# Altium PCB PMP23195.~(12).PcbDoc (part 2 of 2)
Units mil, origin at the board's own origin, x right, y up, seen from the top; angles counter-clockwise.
Board outline 3600 x 3375 mil, 4 copper layers (Top Layer, Signal Layer 1, Signal Layer 2, Bottom Layer), stack 39.6 mil thick; 101 components, 57 nets, 256 pads, 67 vias.
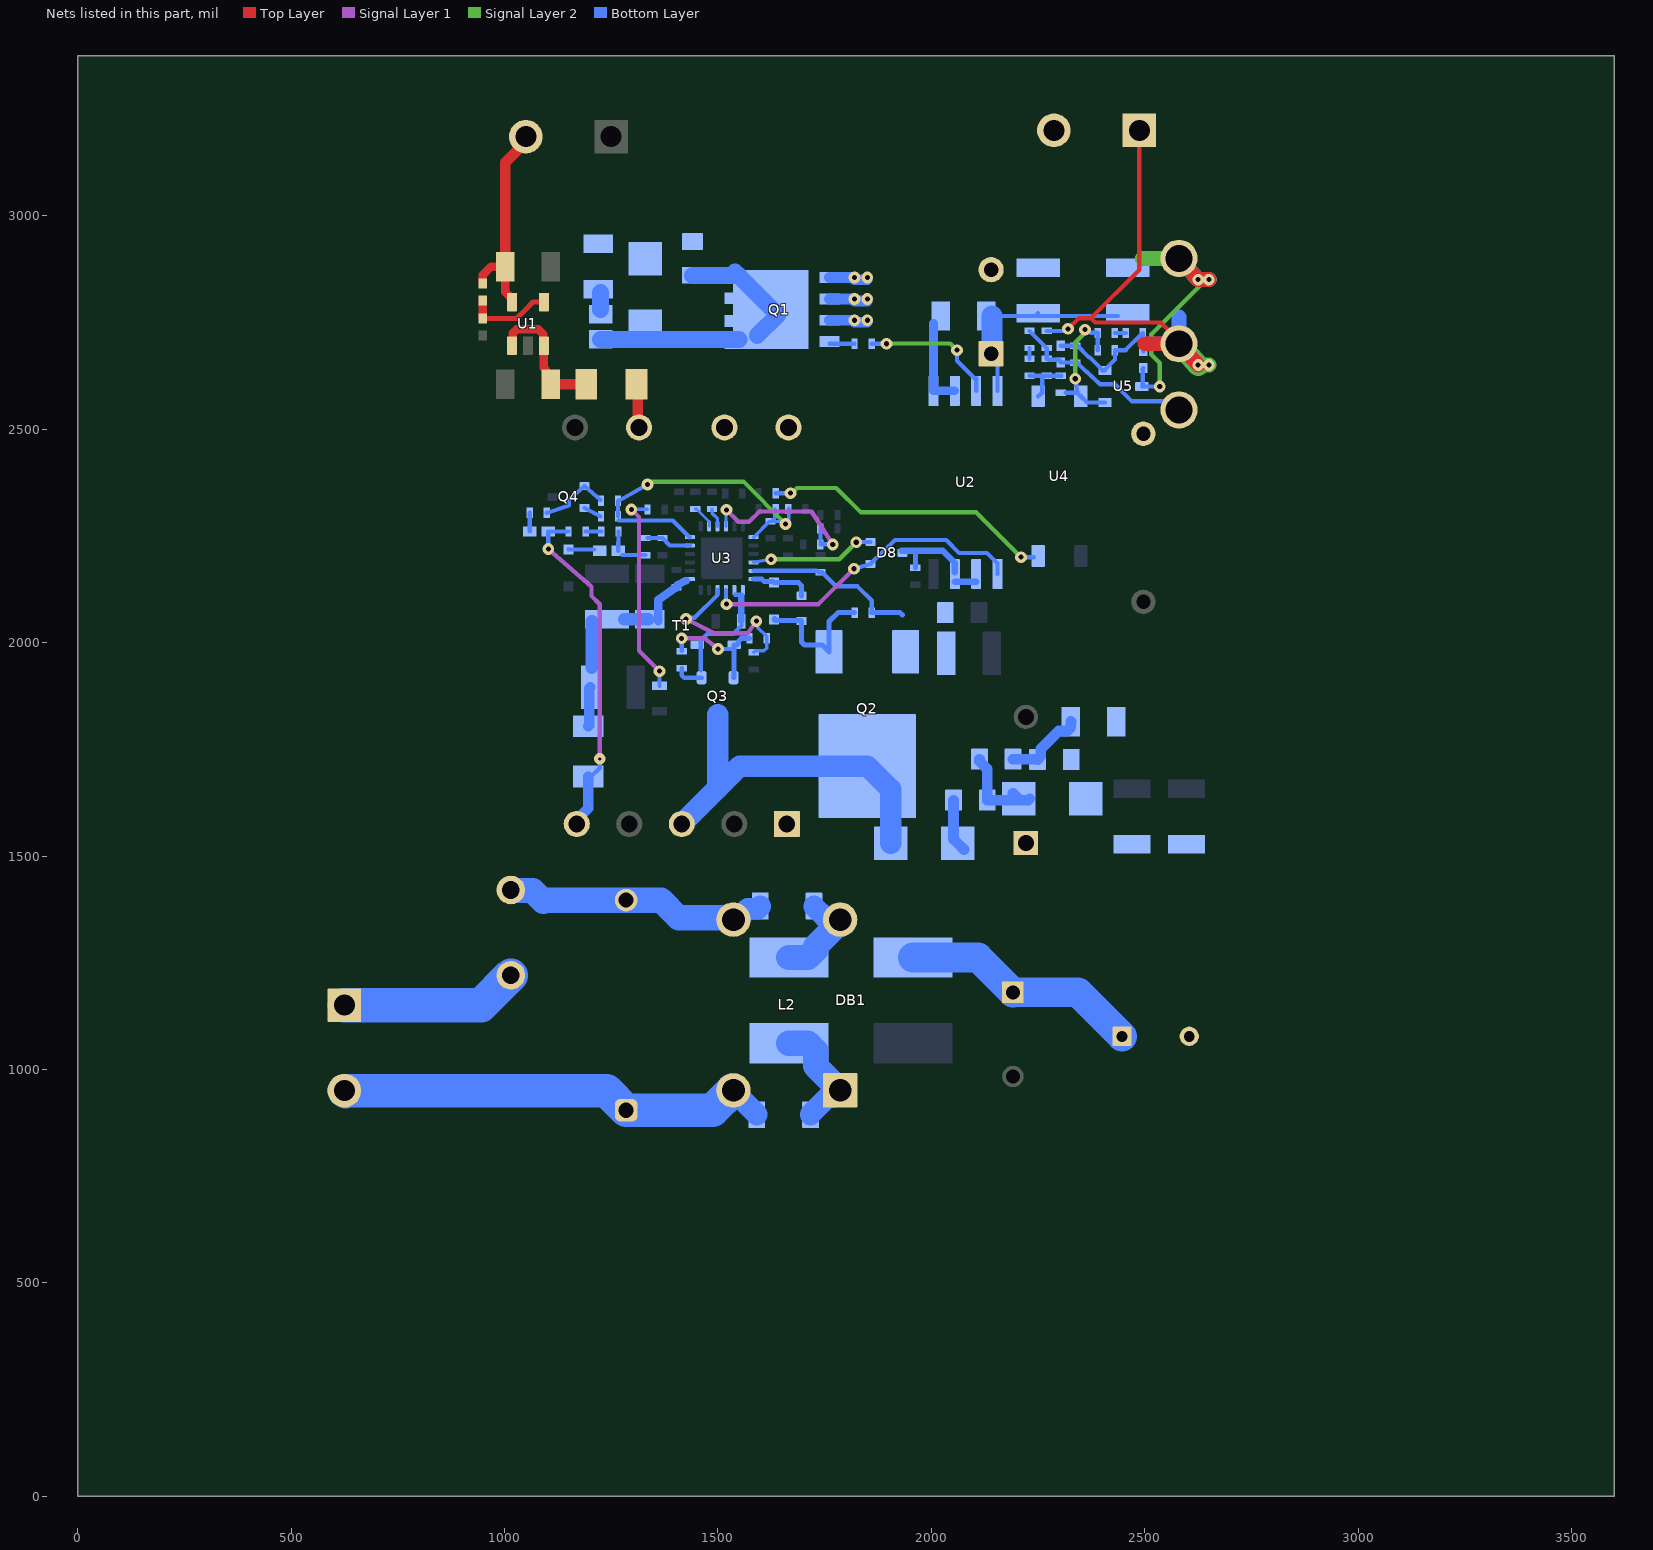
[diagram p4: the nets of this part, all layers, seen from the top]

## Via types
v1: diameter 27.56, hole 11.81, Top Layer to Bottom Layer, tented both sides, 30 vias
v2: diameter 27.56, hole 11.81, Top Layer to Bottom Layer, tented top, 20 vias
v3: diameter 19.68, hole 7.87, Top Layer to Bottom Layer, 5 vias
v4: diameter 24, hole 8, Top Layer to Bottom Layer, tented both sides, 4 vias
v5: diameter 27, hole 8, Top Layer to Bottom Layer, tented both sides, 4 vias
v6: diameter 27.56, hole 11.81, Top Layer to Bottom Layer, 4 vias

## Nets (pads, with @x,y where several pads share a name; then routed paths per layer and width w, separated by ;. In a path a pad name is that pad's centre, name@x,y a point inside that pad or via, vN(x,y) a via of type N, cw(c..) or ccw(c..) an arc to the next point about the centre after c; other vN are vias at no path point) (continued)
GND_S: C1.1 C8.2 C9.2 C10.2 C11.2 C20.2 D4.2 J2.2 Q1.1 Q1.2 Q1.3 R4.1 R36.1 TP2.1 U2.5 U2.6 U5.3 | length 1409.8
  Top Layer w35: TP2.1@2580,2900 v6(2625,2850) v6(2650,2850)
  Signal Layer 1 w35: TP2.1@2580,2900 v6(2625,2850) v6(2650,2850)
  Signal Layer 2 w10: v1(2535,2600) 2535,2655 2515,2675 2515,2722 v6@2641.5,2848.5
  Signal Layer 2 w35: 2495,2900 TP2.1@2580,2900 v6(2625,2850) v6(2650,2850)
  Bottom Layer w10: R36.1@2496.65,2643.31 2494.98,2641.63 2494.98,2601.67 U5.3@2493.31,2600 v1(2535,2600)
  Bottom Layer w20: C20.2@2005,2748.43 U2.5@2005,2589.57 U2.6@2055,2589.57
  Bottom Layer w25: Q1.3@1761.22,2755 v2(1820,2755) ; Q1.2@1761.22,2805 v2(1820,2805) ; Q1.1@1761.22,2855 v2(1820,2855) ; v2@1820,2750 v2@1850,2750 ; v2@1820,2800 v2@1850,2800 ; v2@1820,2850 v2@1850,2850 ; v6(2625,2850) v6(2650,2850)
  Bottom Layer w35: 2495,2900 TP2.1@2580,2900 v6(2625,2850)
  other v2: 1850,2755 1850,2805 1850,2855
IPC: R32.1 R34.2 U3.4 | length 418
  Signal Layer 1 w10: v1(1519.8,2310.91) 1548,2283 1572.52,2283 1597.27,2307 1719,2307 v1(1769,2230)
  Bottom Layer w7.87: U3.4@1518.81,2272.53 1518.81,2309.92 v1(1519.8,2310.91)
  Bottom Layer w10: R32.1@1740,2230 v1@1775,2230 ; R32.1@1740,2235 R34.2@1740,2267
NetC2_2: C2.2 R1.1 R2.2 | length 190.4
  Bottom Layer w25: R2.2@2191.37,1726.98 2191.73,1726.62 2248.45,1726.62 R1.1@2248.81,1726.26 2256,1733.44 2256,1750.87 2298.17,1793.05 2317.7,1793.05 2326.85,1802.2 C2.2@2326.85,1815 C2.2@2326.99,1814.86
NetC6_1: C6.1 J1.2 L2.2 R38.1 | length 1033.3
  Bottom Layer w50: L2.2@1536.31,951.02 1536.31,949.88 1591.01,895.18 R38.1@1591.01,894
  Bottom Layer w78.74: J1.2@627.75,947.72 J1.2@625,950.47 1238.94,950.47 C6.1@1285,904.41 1487.41,904.41 1533.65,950.65 1535.93,950.65 L2.2@1536.31,951.02
NetC6_2: C6.2 F1.1 L2.3 R37.1 | length 629
  Bottom Layer w50: L2.3@1536.31,1351.02 1544.62,1351.02 1570.1,1376.5 1593.9,1376.5 1599.21,1381.82 R37.1@1599.21,1383
  Bottom Layer w59.06: F1.1@1015,1420.47 1016.51,1418.97 1066.03,1418.97 1091,1394 1093.54,1396.54 C6.2@1285,1396.54 1366.83,1396.54 1408.19,1355.17 1532.16,1355.17 L2.3@1536.31,1351.02
NetC7_1: C7.1 DB1.1 L1.1 | length 566.3
  Bottom Layer w70: DB1.1@1957.34,1262.25 2109.18,1262.25 C7.1@2191,1180.43 ; C7.1@2190.68,1180.99 2343.24,1180.99 L1.1@2446.59,1077.65
NetC11_1: C11.1 C12.2 D4.1 Q1.5 Q1.6 Q1.7 Q1.8 Q1.9 T1.8 | length 645.8
  Bottom Layer w39.37: C12.2@1225,2710 1500,2710 1525,2710 Q1.9@1550,2710 ; C11.1@1440,2860 1525,2860 Q1.9@1550,2860 ; Q1.9@1539.77,2868.47 1640.44,2767.8 Q1.9@1592.02,2719.38
NetC12_1: C12.1 R4.2 | length 40
  Bottom Layer w39.37: C12.1@1225,2780 R4.2@1225,2820
NetC15_1: C15.1 D6.1 U1.1 U1.3 | length 318.5
  Top Layer w20: U1.1@1017.6,2695.32 1019.41,2697.13 1019.41,2724.58 1029.31,2734.48 1078.87,2734.48 1090.59,2722.77 1090.59,2697.13 U1.3@1092.4,2695.32 1092.4,2643.67 1096.5,2639.57 1096.5,2616.65 C15.1@1108.15,2605
  Top Layer w25: C15.1@1108.15,2605 D6.1@1191.5,2605
NetC21_1: C21.1 D8.3 U2.2 U2.3 | length 249.6
  Bottom Layer w12: 1960,2215 1962.37,2212.63 C21.1@1962.37,2175
  Bottom Layer w15: D8.3@1930,2215 1960,2215 2027,2215 2055,2186.94 U2.3@2055,2165 ; U2.3@2055,2142 U2.2@2105,2142
NetC24_1: C24.1 R28.2 | length 25
  Bottom Layer w10: R28.2@2230,2665 C24.1@2230,2690
NetC28_1: C28.1 C29.2 R30.1 R35.2 R36.2 U5.2 | length 314.7
  Bottom Layer w10: R30.1@2303.15,2695.35 2303.31,2695.51 C28.1@2333.09,2695.51 ; C28.1@2337.06,2695.67 2333.25,2695.67 C28.1@2333.09,2695.51 ; R36.2@2496.65,2682.68 2496.65,2684.65 2495.83,2685.47 2495.83,2724.17 R35.2@2495,2725 2455,2685 C29.2@2430,2685 2430,2663.13 2406.69,2639.82 U5.2@2406.69,2637.4 2399.71,2637.4 2399.71,2639.46 2371.5,2667.67 2369.55,2667.67 2341.72,2695.51 C28.1@2333.09,2695.51
NetC29_1: C29.1 C30.2 R33.1 U4.3 U5.1 | length 331
  Signal Layer 2 w10: v1(2337,2618) 2337.09,2703 2360,2725.91 v1(2360,2733)
  Bottom Layer w10: R33.1@2315,2585 U4.3@2342.01,2585 ; v1(2337,2618) U4.3@2342.01,2585 ; v1(2360,2733) 2373.02,2725.91 2389.09,2725.91 C30.2@2390,2725 C29.1@2390,2685 ; U5.1@2406.69,2562.6 2364.41,2562.6 U4.3@2350,2577.01 U4.3@2342.01,2585
NetC30_1: C30.1 R35.1 | length 25
  Bottom Layer w10: C30.1@2430,2725 R35.1@2455,2725
NetD1_1: D1.1 R2.1 R3.2 | length 223.6
  Bottom Layer w25: R2.1@2112.63,1726.98 2112.63,1722.05 2130.66,1704.02 R3.2@2130.66,1630.74 2227,1630.74 D1.1@2230.63,1634.37 ; D1.1@2191.26,1647.37 D1.1@2204.26,1634.37
NetD2_1: D2.1 R3.1 | length 125.8
  Bottom Layer w25: R3.1@2051.92,1630.74 2051.92,1539.83 D2.1@2061.92,1529.83 D2.1@2076.57,1515.19
NetD5_2: D5.2 Q2.1 R6.2 R7.2 | length 331.4
  Bottom Layer w12: D5.2@1632.97,2055.66 D5.2@1631,2053.69 1632.61,2052.08 1694.39,2052.08 R6.2@1696,2050.47 1696,2001.51 1703.03,1994.48 1744.12,1994.48 Q2.1@1760.24,1978.37 1760.24,2049.24 1781,2070 R7.2@1820.31,2070
NetD6_2: D6.2 T1.7 | length 103.4
  Top Layer w25: D6.2@1309.61,2605 1312.46,2602.15 1312.46,2506.85 T1.7@1315.31,2504
NetD7_1: D7.1 Q3.2 R8.1 R12.2 | length 280.8
  Signal Layer 1 w10: v1(1415,2010) 1468.25,2010 v1(1500,1985)
  Bottom Layer w10: R8.1@1415,1980 v1(1415,2010) ; v1(1500,1985) 1535,1985
  Bottom Layer w12: Q3.2@1536.6,1917.76 1537.45,1918.61 1537.45,1994.15 1543.36,1994.15 1548.06,1998.84 1548.06,2002.97 1555.08,2010 R12.2@1573.9,2010
NetD9_1: D9.1 R17.2 R19.1 | length 99
  Bottom Layer w10: D9.1@1266.65,2215 R17.2@1267,2260 ; D9.1@1276,2205 R19.1@1330,2205
NetD9_2: D9.2 D11.2 | length 60
  Bottom Layer w10: D11.2@1150,2218.31 D9.2@1210,2218
NetD10_1: D10.1 R20.2 | length 44
  Bottom Layer w10: R20.2@1059,2304 D10.1@1059.35,2260
NetDB1_2: DB1.2 L2.4 R37.2 | length 240.2
  Bottom Layer w50: R37.2@1725.2,1383 1725.2,1381.82 1750.12,1356.9 1780.43,1356.9 L2.4@1786.31,1351.02
  Bottom Layer w59.06: DB1.2@1666,1262.25 1711.28,1262.25 1728.99,1279.96 1728.99,1287.85 1786.31,1345.16 L2.4@1786.31,1351.02
NetDB1_3: DB1.3 L2.1 R38.2 | length 280.4
  Bottom Layer w50: R38.2@1716.99,894 1716.99,895.18 1757.48,935.67 1770.95,935.67 L2.1@1786.31,951.02
  Bottom Layer w59.06: DB1.3@1666,1061.46 1711.28,1061.46 1728.99,1043.74 1728.99,1008.34 L2.1@1786.31,951.02
NetF1_2: F1.2 J1.1 | length 419
  Bottom Layer w80: J1.1@625,1150.47 945,1150.47 F1.2@1015,1220.47
NetQ1_4: Q1.4 R5.2 | length 58.8
  Bottom Layer w10: Q1.4@1761.22,2700 R5.2@1820,2700
NetQ4_1: Q4.1 R16.2 R20.1 | length 166.2
  Bottom Layer w10: R20.1@1099,2304 1150.94,2321 1150.94,2335 Q4.1@1187.42,2366.59 R16.2@1224.37,2334
NetQ4_2: Q4.2 R15.2 | length 41.7
  Bottom Layer w10: Q4.2@1187.42,2315.41 R15.2@1224.37,2296
NetR9_1: R9.1 R13.2 U1.4 | length 201.9
  Top Layer w12: R13.2@949,2758.98 1028.16,2758.98 1047.9,2778.72 1066.86,2797.68 U1.4@1092.4,2797.68
  Top Layer w20: R13.2@949,2758.98 R9.1@949,2801.49
NetR14_2: R14.2 R17.1 | length 37
  Bottom Layer w10: R14.2@1190,2260 R17.1@1227,2260
NetR26_1: R26.1 R28.1 R33.2 U4.1 | length 127.8
  Bottom Layer w10: R28.1@2230,2625 R26.1@2270,2625 R33.2@2305,2625 ; U4.1@2250,2577.01 2260,2585 R26.1@2260,2625
OPTO_C: R21.2 U4.6 | length 676
  Signal Layer 2 w10: v1(1670,2350) 1685,2362 1777,2362 1835,2305 2105,2305 v2(2210,2200)
  Bottom Layer w10: R21.2@1635,2350 v1(1670,2350) ; v2(2210,2200) U4.6@2240,2200
P13: C23.1 D7.2 Q3.1 R8.2 U3.13 U3.14 | length 320.3
  Bottom Layer w10: R8.2@1415,1940 1415,1923.61 1420.86,1917.76 Q3.1@1461.79,1917.76 ; 1460,1935 1460,2005 1475,2020 1535,2020 C23.1@1555,2040 ; U3.14@1540,2112 U3.13@1556.22,2111.97
  Bottom Layer w15: C23.1@1555,2050 1555,2109
PWML: D5.1 R6.1 U3.12 | length 142.3
  Bottom Layer w12: U3.12@1583.77,2148.51 1602.65,2148.51 1608.39,2142.77 1628.53,2142.77 D5.1@1631,2140.31 1688.97,2140.31 1696,2133.28 R6.1@1696,2109.53
QLSRC: Q2.3 R7.1 R10.1 R11.2 R23.2 U3.11 | length 408.3
  Bottom Layer w10: U3.11@1583.77,2168.2 1731.71,2168.2 1735.5,2164.41 R23.2@1740,2164.41 1744.5,2164.41 1777.22,2131.69 1827.2,2131.69 1860.31,2098.59 R7.1@1860.31,2070
  Bottom Layer w12: R7.1@1860.31,2070 1926.91,2070 1932.4,2064.5
RDM: R31.2 U3.3 | length 45.8
  Bottom Layer w7.87: R31.2@1485.96,2312.88 1485.96,2303.52 1499.12,2290.36 U3.3@1499.12,2272.53
REF: C22.1 C31.1 R15.1 R16.1 R24.1 U3.7 U3.24 | length 839.7
  Signal Layer 2 w9.84: 1560,2377 v1(1658,2278) ; v1@1659.44,2269.49 v1@1664.53,2274.58
  Signal Layer 2 w10: v1@1340,2377 1560,2377
  Bottom Layer w8: U3.7@1583.77,2246.94 1620.5,2283.67 C31.1@1624.99,2283.67 ; C22.1@1634.9,2312.88 1632.61,2312.88 1632.61,2291.29 C31.1@1624.99,2283.67 ; R24.1@1665.76,2314.85 1665.76,2275.81 1664.53,2274.58 1655.44,2283.67 C31.1@1624.99,2283.67
  Bottom Layer w9.84: U3.24@1432.72,2246.94 U3.24@1434.16,2246.94
  Bottom Layer w10: R15.1@1266,2296 R16.1@1266,2332 ; R16.1@1266,2331 v1(1335,2370) ; R15.1@1267.65,2286 1394,2286 U3.24@1432.72,2246.94
RT1_1: R27.1 RT1.1 | length 487.6
  Signal Layer 1 w9.84: v1(1297,2312) 1315,2294 ; v1@1297.34,2310.91 v1@1306.49,2310.91
  Signal Layer 1 w10: 1315,2294 1315,1981 v1(1363,1933)
  Bottom Layer w8: v1(1297,2312) R27.1@1335,2312
  Bottom Layer w10: RT1.1@1362.93,1898.9 v1(1363,1933)
RTZ: R29.2 U3.2 | length 56
  Bottom Layer w6: R29.2@1446.59,2312.88 1450.15,2312.88 1479.44,2283.59 U3.2@1479.44,2272.53
RUN: D8.2 U3.10 | length 301.1
  Signal Layer 2 w9.84: v1(1624.74,2195.03) 1784,2195
  Signal Layer 2 w10: 1784,2195.03 v1(1824,2235)
  Bottom Layer w7.87: U3.10@1583.77,2187.88 v1(1624.74,2195.03) v1@1617.59,2187.88
  Bottom Layer w10: v1(1824,2235) D8.2@1857.6,2235.59
SR_DRV: R5.1 U2.7 | length 325.9
  Signal Layer 2 w10: v1(1895,2700) 1895.7,2700.7 2044.3,2700.7 v1(2060,2685)
  Bottom Layer w10: R5.1@1860,2700 v1(1895,2700) ; v1(2060,2685) 2060,2660 U2.7@2105,2615 ; U2.7@2105,2589.57 U2.7@2105,2620
SRDRV: D8.1 U2.1 U3.15 | length 773.7
  Signal Layer 1 w10: v1(1520,2090) 1735.67,2090 v1(1818.64,2172.96)
  Bottom Layer w10: v1@1519,2090 U3.15@1519,2123 ; v1(1818.64,2172.96) D8.1@1857.6,2184.41 1915,2240 2035,2240 2065,2210 2130,2210 U2.1@2155,2185 ; U2.1@2155,2160.43 U2.1@2155,2184.84
SWS: C16.2 R12.1 U3.16 | length 403.4
  Signal Layer 1 w10: v1(1425,2055) 1490,2022 1570,2022 v1(1590,2050)
  Bottom Layer w8: C16.2@1583.77,1977 1587.27,1980.5 1607.58,1980.5 1613.9,1986.82 R12.1@1613.9,2010 1613.9,2014.5 1593.74,2034.66 1593.74,2046.26 v1(1590,2050)
  Bottom Layer w10: v1(1425,2055) 1428.36,2058.36 1445.8,2058.36 1499.12,2111.68 U3.16@1499.12,2122.92
Vaux: D3.2 D10.2 R14.1 T1.5 | length 812.7
  Signal Layer 1 w10: v1(1102.65,2219) 1204,2130.77 1204,2109.23 1223.35,2089.88 v5(1223.35,1727.31)
  Bottom Layer w10: v1(1102.65,2219) D10.2@1102.65,2260 R14.1@1150,2260 ; D3.2@1196.18,1685.94 1202.76,1685.94 1223.35,1706.54 v5(1223.35,1727.31)
  Bottom Layer w25: T1.5@1169.31,1575 1169.31,1584.75 1196.18,1611.62 D3.2@1196.18,1685.94
Vbulk: C2.1 C3.2 C4.2 C5.2 D1.2 L1.2 R1.2 T1.1
VDD: C13.2 C17.1 C18.1 C19.2 D3.1 U3.19 | length 380.9
  Bottom Layer w18: C17.1@1405,2135 U3.19@1425,2145
  Bottom Layer w20: C18.1@1360,2050 1360,2100 C17.1@1403,2130
  Bottom Layer w25: D3.1@1196.18,1804.06 1198.59,1806.46 1198.59,1892.59 C13.2@1201,1895
  Bottom Layer w30: C13.2@1204.46,1941.82 C19.2@1205,2050 ; C19.2@1281.04,2054.85 C18.1@1336.04,2054.85
VOUT: C8.1 C9.1 C10.1 C20.1 J2.1 R18.1 T1.9 TP1.1 U2.8 | length 1910.8
  Top Layer w10: v1(2320,2735) 2346,2760 2374,2760 ; J2.1@2487,3200 2487,2873 2374,2760 ; TP1.1@2580,2700 2580,2706.97 2537.36,2750 2384,2750.05 2374,2760
  Top Layer w20: v6(2625,2650) v6(2650,2650)
  Top Layer w35: 2500,2700 TP1.1@2580,2700 v6(2625,2650)
  Signal Layer 1 w20: v6(2625,2650) v6(2650,2650)
  Signal Layer 1 w35: 2505,2700 TP1.1@2580,2700 v6(2625,2650)
  Signal Layer 2 w35: v6(2625,2650) v6(2650,2650)
  Signal Layer 2 w50: TP1.1@2580,2700 v6(2625,2650)
  Bottom Layer w10: C10.1@2141.93,2678.5 C10.1@2140,2676.57 2155,2661.57 U2.8@2155,2589.57 ; C20.1@2141.93,2765 C8.1@2243.15,2765 ; C8.1@2250,2771.85 C8.1@2243.15,2765 ; R18.1@2270,2730 2310,2730 v1(2320,2735) ; C9.1@2436.8,2765 C8.1@2243.15,2765
  Bottom Layer w25: v6@2625.32,2650 v6(2650,2650)
  Bottom Layer w35: 2580,2762.93 TP1.1@2580,2700 v6(2625,2650)
  Bottom Layer w50: C10.1@2141.93,2678.5 C20.1@2141.93,2765
VOUT2: C14.1 J3.2 R9.2 U1.5 | length 496.5
  Top Layer w20: R9.2@949,2840.86 949,2861.29 968.54,2880.83 C14.1@1001.85,2880.83 1001.85,2821.05 1013.57,2809.34 1015.79,2809.34 1017.6,2807.53 U1.5@1017.6,2797.68
  Top Layer w25: C14.1@1001.85,2880.83 1001.85,3124.44 1050,3172.59 J3.2@1050,3185
VOUT_A: C24.2 C28.2 R18.2 R26.2 R30.2 TP3.1 | length 443.3
  Bottom Layer w10: C24.2@2230,2730 R18.2@2270,2690 R26.2@2270,2666.65 ; R26.2@2270,2665 R26.2@2270,2666.65 ; R30.2@2303.15,2655.98 R30.2@2303.15,2657.66 ; TP3.1@2580,2545 2560,2565 2470,2565 2430,2605 2395.28,2605 2365,2634 2363.23,2634 2341.4,2655.83 2304.98,2655.83 R30.2@2303.15,2657.66 ; R26.2@2270,2666.65 2274.15,2662.5 2298.31,2662.5 R30.2@2303.15,2657.66
VS: R19.2 R22.2 U3.23 | length 106.7
  Bottom Layer w10: R19.2@1335,2245 R22.2@1370,2245 1387,2227.25 U3.23@1434.16,2227.25
Vswn: D2.2 Q2.2 Q3.3 T1.3 | length 866.5
  Bottom Layer w50: T1.3@1415.31,1575 1499.2,1658.89 ; Q3.3@1499.2,1831.14 1499.2,1658.89 ; D2.2@1904.44,1529.83 1904.44,1656.21 Q2.2@1850,1710.65 1550.96,1710.65 1499.2,1658.89
pads on no net: T1.2

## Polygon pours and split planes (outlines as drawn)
GND_P on Bottom Layer "BOTTOM_LAYER_GND_P_P296" (solid, remove dead copper, pour order 296): 2598.51,1797 2634.79,1797 2635.32,1870 2635.32,2030 2000.93,2030 2000.93,1797
GND_S on Bottom Layer "BOTTOM_LAYER_GND_S_P335" (solid, remove dead copper, pour order 335): 2239.06,3375 2670.99,3375 2670.99,2938 2239.06,2938
NetC11_1 on Bottom Layer "BOTTOM_LAYER_NETC11_1_P334" (solid, remove dead copper, pour order 334): 1434.16,2678.5 1432.72,2677.07 1432.72,2519.75 1487.47,2465 1535,2465 1583.77,2513.77 1583.77,2675.67
Vbulk on Bottom Layer "BOTTOM_LAYER_VBULK_P330" (solid, remove dead copper, pour order 330): 2190.68,1486.26 2356.95,1320 2424.5,1320 2540,1204.5 2540,1050 2566.21,1023.79 2647.11,1023.79 2647.11,1480.01
GND_P on Bottom Layer "BOTTOM_LAYER_GND_P_P329" (solid, remove dead copper, pour order 329): 1254.15,1948.15 1246.95,1940.96 1246.95,1847.07 1260,1834.03 1260,1548.88 1269.05,1539.83 1322.66,1539.83 1339,1556.17 1339,1766.86 1394,1821.86 1394,1857.51 1381.51,1870 1360,1870 1360,1870.82 1339,1891.82 1339,1957 1261.03,1957 1254.15,1950.12
GND_P on Bottom Layer "BOTTOM_LAYER_GND_P_P328" (solid, remove dead copper, pour order 328): 2091.29,2117.58 2091.29,1970.89 2087.98,1967.58 2088.48,1967.08 2260,1967.08 2260,2002 2134.99,2127.01 2134.18,2126.2 2085.15,2126.2
GND_P on Bottom Layer "BOTTOM_LAYER_GND_P_P306" (solid, remove dead copper, pour order 306): 1950,2150 1950,2098.54 2147.09,2098.54 2147.09,2150
QLSRC on Bottom Layer "BOTTOM_LAYER_QLSRC_P327" (solid, remove dead copper, pour order 327): 2072.02,2102.03 1907.03,2102.03 1888.41,2083.41 1888.41,1922.4 1895,1915.82 2056.89,1915.82 2072.02,1930.95
GND_P on Bottom Layer "BOTTOM_LAYER_GND_P_P325" (solid, remove dead copper, pour order 325): 2401.69,1611.26 2401.69,1704.56 2429.56,1704.56 2479.8,1754.8 2479.8,2030 2482.14,2027.66 2647.11,2027.66 2647.11,1611.26
Vbulk on Bottom Layer "BOTTOM_LAYER_VBULK_P324" (solid, remove dead copper, pour order 324): 2401.69,1611.26 2650.36,1611.26 2652.27,1609.35 2650,1607.07 2650,1469.17 2207.78,1469.17 2204.26,1472.69 2342.26,1610.69 2342.84,1610.69
Vbulk on Bottom Layer "BOTTOM_LAYER_VBULK_P323" (solid, remove dead copper, pour order 323): 2380,1850.43 2380,1767.48 2367.32,1754.8 2308.08,1754.8 2282.13,1728.85 2282.13,1608 2221.3,1547.17 2203.01,1547.17 2190.68,1534.85 2190.68,1486.26 2204.26,1472.69 2282.85,1472.69 2420,1609.83 2420,1695 2470,1745 2470,1850.06
GND_P on Bottom Layer "BOTTOM_LAYER_GND_P_P319" (solid, remove dead copper, pour order 319): 1867.07,1151.02 2066.22,1151.02 2117.25,1100 2242.34,1100 2252.34,1090 2252.34,952.34 2230,930 1909.76,930 1867.07,972.69
VOUT on Bottom Layer "BOTTOM_LAYER_VOUT_P314" (solid, remove dead copper, pour order 314): 2655,2820 2655,2630 2515,2630 2515,2755 2110,2755 2110,2820
NetC11_1 on Bottom Layer "Bottom Layer-NetC33_2" (solid, pour order 303): 1395,2660 1395,2900 1720,2900 1720,2660
GND_S on Bottom Layer "Bottom Layer-SGND" (solid, remove dead copper, pour order 307): 1184.57,2980 1184.57,2915 1733.02,2915 1733.02,2726.26 2050,2726.26 2050,2830 2655,2830 2655,2960 2635,2980
GND_S on Signal Layer 2 "SIGNAL_LAYER_2_GND_S_P338" (solid, remove dead copper, pour order 338): 2260,3375 2260,2869.98 2653,2869.98 2653,3375
GND_S on Signal Layer 2 "Signal Layer 2-SGND" (solid, pour order 292): 1274.79,2823.51 1274.79,2672.12 1471.92,2475 2495,2475 2495,2725 2605,2835 2654,2835 2654,2915 2654,2965 2638.62,2980.38 1431.33,2980.05
GND_P on Signal Layer 2 "SIGNAL_LAYER_2_GND_P_P293" (solid, remove dead copper, pour order 293): 1374.42,2365 1374.42,1541.23 2650,1541.23 2650,2143.51 2428.51,2365
GND_P on Signal Layer 2 "SIGNAL_LAYER_2_GND_P_P291" (solid, remove dead copper, pour order 291): 928,2390 928,1545.17 1765.07,1545.17 1769.08,2390
GND_P on Signal Layer 2 "SIGNAL_LAYER_2_GND_P_P290" (solid, remove dead copper, pour order 290): 1900.33,1576.66 1900.33,880 2650,880 2650,1576.66
VOUT on Signal Layer 1 "SIGNAL_LAYER_1_VOUT_P337" (solid, remove dead copper, pour order 337): 2372.3,2945.9 2374,2947.6 2374,3380.9 2680.61,3380.9 2673.28,3373.57 2673.28,2646.11 2662.31,2657.08 2386.29,2657.08
GND_C on Signal Layer 1 "SIGNAL_LAYER_1_GND_C_P332" (solid, remove dead copper, pour order 332): 1354.15,3375 1357.21,3371.94 1357.21,2988.15 1158.7,2988.15 1151.5,2980.95 1151.5,2564.5 1241,2475 920.01,2475 911.21,2483.81 911.21,3375
GND_P on Signal Layer 1 "SIGNAL_LAYER_1_GND_P_P289" (solid, remove dead copper, pour order 289): 1416.08,2301.91 1416.08,1540.41 2650,1540.41 2650,2301.91
VOUT on Signal Layer 1 "Signal Layer 1-VN" (solid, pour order 288): 1363,2519.02 1407.02,2475 2510,2475 2655,2620 2655,2747 2432,2970 1363,2970
GND_P on Signal Layer 1 "SIGNAL_LAYER_1_GND_P_P287" (solid, remove dead copper, pour order 287): 928,2389 928,1545.17 1781,1545.17 1781,2389
no net on Signal Layer 1 "SIGNAL_LAYER_1_NONET_P286" (solid, remove dead copper, pour order 286): 1900.33,1494 1900.33,880 2650,880 2650,1494
VOUT on Top Layer "TOP_LAYER_VOUT_P336" (solid, remove dead copper, pour order 336): 2374,2940 2375.7,2941.7 2375.7,3375 2682.31,3375 2674.99,3367.67 2674.99,2640.21 2664.01,2651.18 2387.99,2651.18
GND_C on Top Layer "TOP_LAYER_GND_C_P331" (solid, remove dead copper, pour order 331): 1150,3375 1118.14,3343.14 1118.14,3151.17 946.9,2979.93 915.01,2948.04 915.02,2450 920.02,2445 1265,2445 1261.03,2448.97 1261.03,2619.17 1134.5,2745.7 1134.5,2988.15 1166.35,3020 1190,3020 1341.02,3020 1354.5,3033.48 1354.5,3375
Vbulk on Top Layer "TOP_LAYER_VBULK_P322" (solid, remove dead copper, pour order 322): 1598.5,1545.17 1600,1546.67 1600,1633.29 1621.71,1655 2284.35,1655 2330,1609.35 2330,1485 2283,1438 2282.13,1438.87 1902.84,1438.87 1827.2,1514.5 1624.74,1514.5
VOUT on Top Layer "Top Layer-VN" (solid, pour order 285): 1150,2975 1150,2730.42 1246.95,2660 1600,2660 1600,2465 2500,2465 2655,2620 2655,2745 2425,2975
GND_P on Top Layer "TOP_LAYER_GND_P_P283" (solid, remove dead copper, pour order 283): 1775,2226.84 1775,1755.92 2635.32,1755.78 2635.32,2075.51 2483.98,2226.84
GND_P on Top Layer "TOP_LAYER_GND_P_P284" (solid, remove dead copper, pour order 284): 940,2390 940,1887.57 1860,1887.57 1860,2390

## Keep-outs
Keep-Out Layer:
  text ".Layer_Name" at 577,-858.49 h60

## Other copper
Top Layer:
  pour cut-out: 1245,2270 1447.21,2270 1447.21,2185.87 1347.46,2185.87 1339.83,2193.5 1245,2193.5
  pour cut-out: 2374,2772.45 2468.81,2872.24 2474,2877.44 2474,3159 2496.65,3159 2496.65,2872.24 2389.97,2765.56 2389.97,2763.03
  pour cut-out: 2380.55,2772.45 2389.97,2763.03 2547.64,2763.03 2570.31,2740.59 2547,2717.28 2529,2736.67 2358.7,2736.67 2336.23,2714.2 2295.79,2714.2 2295.79,2747.13 2318.85,2772.45
  pour cut-out: 1431.86,2328 1509,2328 1509,2259 1470,2259 1470,2284.16 1453.16,2301 1431.86,2301
  pour cut-out: 1285,2145 1205,2145 1205,2095 1235,2095 1285,2095
  pour cut-out: 1235,1930 1285,1930 1285,1845 1235,1845
  text ".Layer_Name" at 577,-858.49 h60
Signal Layer 1:
  pour cut-out: 1245,2270 1447.21,2270 1447.21,2185.87 1347.46,2185.87 1339.83,2193.5 1245,2193.5
  pour cut-out: 1245,2270 1447.21,2270 1447.21,2185.87 1347.46,2185.87 1339.83,2193.5 1245,2193.5
  pour cut-out: 2296.39,2714.17 2345,2714.17 2345,2758.48 2296.39,2758.51
  pour cut-out: 1432,2328.11 1509,2328.11 1509,2259 1470,2259 1470,2284.16 1453.16,2301 1432,2301
  pour cut-out: 1285,2145 1205,2145 1205,2095 1235,2095 1235,1845 1285,1845
Signal Layer 2:
  pour cut-out: 1245,2270 1447.21,2270 1447.21,2185.87 1347.46,2185.87 1339.83,2193.5 1245,2193.5
  pour cut-out: 1245,2270 1447.21,2270 1447.21,2185.87 1347.46,2185.87 1339.83,2193.5 1245,2193.5
  pour cut-out: 1245,2270 1447.21,2270 1447.21,2185.87 1347.46,2185.87 1339.83,2193.5 1245,2193.5
  pour cut-out: 1432,2328 1509,2328 1509,2259 1470,2259 1470,2283 1452,2301 1432,2301
  pour cut-out: 1235,1930 1285,1930 1285,1845 1235,1845
  pour cut-out: 1285,2145 1205,2145 1205,2095 1235,2095 1285,2095
Bottom Layer:
  text ".Layer_Name" at 577,-858.49 h60

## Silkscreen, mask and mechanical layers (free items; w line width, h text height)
Top Overlay:
  lines w6: 1107.26,897.53 1441.9,897.53 1441.9,1488.08 1107.26,1488.08 1107.25,897.53
  lines w7: 950,1650 950,1710
  lines w7.87: 1148.49,2393.06 1148.49,2459.5
  lines w10: 40,910 60,850 ; 40,2935 60,2995 ; 50,850 70,850 ; 50,2995 70,2995 ; 60,1647.58 60,850 ; 60,2197.42 60,2995 ; 80,910 60,850 ; 80,2935 60,2995 ; 867,3176 917,3176 ; 892,3151 892,3201 ; 915,740 915,760 ; 975,730 915,750 ; 975,770 915,750 ; 1376.6,3180.05 1426.6,3180.05 ; 1520.08,750 915,750 ; 2069.92,750 2675,750 ; 2121.07,3190 2171.07,3190 ; 2605.5,3190 2655.5,3190 ; 2615,730 2675,750 ; 2615,770 2675,750 ; 2630.5,3165 2630.5,3215 ; 2675,740 2675,760
  lines w30: 2055.47,2956.27 cw(c2140,2775) 2224.52,2956.27 ; 2107.25,902.57 ccw(c2191.77,1083.83) 2276.3,902.57
  text "DC Output" at 1471,3272 h90
  text "DC Output" at 2734,3264 h90
  text "5V,0.2A" at 1493,3168 h90
  text "12V,1.5A" at 2756,3160 h90
  text "GND_S" at 2310,2915 h40
  text "B" at 1487,2660 h40
  text "A" at 1717,2660 h40
  text "VOUT" at 2350,2645 h40
  text "2145 (mil)" at 94.99,1657.58 h60 r90
  text "+" at 2340,1270 h60
  text "LINE" at 307.73,1180 h40
  text "NEUT" at 307.73,980 h40
  text "J1: AC Input" at 250,820 h90
  text "1760 (mil)" at 1530.08,715.01 h60
  text "DANGER HIGH VOLTAGE" at 1371,577 h100
  text ".Layer_Name" at 577,-858.49 h60
Bottom Overlay:
  lines w5: 1316,2389 1315.5,2292 1325,2262 ; 1402,1993 1432,1993 ; 1412.17,2075 1441.83,2075 ; 1588.78,2399 1597,2372 ; 1638.09,2287.18 1650,2295 1650,2360 1639.83,2376 ; 1667,2034 1677,1986 ; 1719,2249 1719,2351 ; 1775.98,2318.91 1803,2340 ; 1790,2281 1814,2304 ; 2287,2678 2298.88,2739 ; 2289,2729 2316.67,2757 ; 2300.5,2569 2316.78,2548 2383,2548 2399.37,2529 ; 2329,2706.59 2351.39,2759 ; 2370,2713 2383,2750.05 2383,2836 ; 2395,2745 2395,2910 ; 2510,2725 2535,2745 ; 2511,2679 2530,2661
  lines w7: 1422,2265 1422,2284 ; 1422,2285 1442,2285
  lines w7.87: 1613.91,1351.81 1750,1352
  lines w8: 2355,1320 2385,1320 ; 2370,1305 2370,1335
  text "B" at 1387,2560 h40
  text "A" at 1870,2560 h40
  text "CAUTION" at 3400,2100 h100
  text "HOT SURFACE" at 3405,2010 h100
  text "DANGER" at 774,1372 h100
  text "HIGH VOLTAGE" at 773,1286 h100
  text "L" at 1111,1169 h100
  text "TP1" at 1110,1110 h72.83
  text "TP2" at 1110,1000 h72.83
  text "N" at 1120,916 h100
  text "DANGER" at 3500,850 h100
  text "HIGH VOLTAGE" at 3500,750 h100
  text ".Layer_Name" at 577,-858.49 h60
Top Paste:
  text ".Layer_Name" at 577,-858.49 h60
Bottom Paste:
  text ".Layer_Name" at 577,-858.49 h60
Top Solder:
  text ".Layer_Name" at 577,-858.49 h60
  text ".Layer_Name" at 577,-858.49 h60
Bottom Solder:
  text ".Layer_Name" at 577,-858.49 h60
Drill Guide:
  text ".Layer_Name" at 577,-858.49 h60
M1 Board Outline:
  drawing of 275 lines, arcs and shapes, not listed
  text ".Layer_Name" at 577,-858.49 h60
M2 Board Dimensions:
  rectangle: 125,-400 500,-275
  rectangle: 0,-275 125,-150
  lines w7: 0,-275 1000,-275 ; 125,-400 125,-150 ; 250,-400 250,-150 ; 500,-400 500,-150 ; 750,-400 750,-150 ; 0,-400 0,-150 1000,-150 1000,-400 0,-400
  text ".Layer_Name" at 577,-858.49 h60
M3 3D STEP Top:
  text ".Layer_Name" at 577,-858.49 h60
M4 3D STEP Bottom:
  text ".Layer_Name" at 577,-858.49 h60
M5 Assembly Top:
  lines w10: -292,-930.17 6308,-930.17 ; -292,-726.83 6310,-726.83 ; -292,-523.5 -292,-1133.5 3713,-1133.5 6310,-1133.5 6310,-523.5 -291.5,-523.5 -291.5,-1133.5 1284,-1133.5 ; 2173,-1133.5 2173,-523.5 ; 3440,-726.83 3440,-523.5 ; 4280,-726.83 4280,-523.5 ; 4902,-1140 4902,-937.17
  text "COMPONENTS MARKED 'DNP' SHOULD NOT BE POPULATED." at 1153.5,-318.5 h60
  text "ASSEMBLY VARIANT:" at 1153,-434 h60
  text ".VariantName" at 2189,-434 h60
  text "PCB VIEWED FROM TOP SIDE" at -228.5,-655.67 h60
  text "BOARD #:" at 2248,-655.67 h60
  text ".PRJ_Number" at 2793.5,-655.67 h60
  text "REV:" at 3638,-655.67 h60
  text ".PCB_Rev" at 3929.5,-655.67 h60
  text "SVN REV:" at 4476,-655.67 h60
  text ".VersionControl_RevNumber" at 4982,-655.67 h60
  text "TID #:" at 2248,-859 h60
  text ".TID" at 2793.5,-859 h60
  text "PLOT NAME =" at -228.5,-1064.34 h60
  text ".plot_File_Name" at 577,-1064.34 h60
  text "GENERATED    :" at 2250,-1064.34 h60
  text ".Print_Date" at 3119.5,-1064.34 h60
  text ".Print_Time" at 3848.5,-1064.34 h60
  text "TEXAS INSTRUMENTS" at 5113,-1064.34 h60
M6 Assembly Bottom:
  lines w10: -292.5,-727.33 6309.5,-727.33 ; -290.5,-930.67 6309.5,-930.67 ; 1115.5,-1140.5 1115.5,-937.67 ; 1737.5,-727.33 1737.5,-524 ; 2577.5,-727.33 2577.5,-524 ; 3844.5,-1134 3844.5,-524 ; 4733.5,-1134 6309,-1134 6309,-524 -292.5,-524 -292.5,-1134 2304.5,-1134 6309.5,-1134 6309.5,-524
  text "COMPONENTS MARKED 'DNP' SHOULD NOT BE POPULATED." at 6102,-318 h60
  text ".VariantName" at 5058,-434 h60
  text "ASSEMBLY VARIANT:" at 6097,-434 h60
  text ".VersionControl_RevNumber" at 1035.5,-656.17 h60
  text "SVN REV:" at 1541.5,-656.17 h60
  text ".PCB_Rev" at 2088,-656.17 h60
  text "REV:" at 2379.5,-656.17 h60
  text ".PRJ_Number" at 3224,-656.17 h60
  text "BOARD #:" at 3769.5,-656.17 h60
  text "PCB VIEWED FROM BOTTOM SIDE" at 6246,-656.17 h60
  text ".TID" at 3224,-859.5 h60
  text "TID #:" at 3769.5,-859.5 h60
  text "TEXAS INSTRUMENTS" at 904.5,-1064.84 h60
  text ".Print_Time" at 2169,-1064.84 h60
  text ".Print_Date" at 2898,-1064.84 h60
  text "GENERATED    :" at 3767.5,-1064.84 h60
  text ".plot_File_Name" at 5440.5,-1064.84 h60
  text "PLOT NAME =" at 6246,-1064.84 h60
M9 Title Sheet:
  drawing of 57 lines, arcs and shapes, not listed
  text "1" at 739.84,8036.5 h70
  text "2" at 3235.5,8036.5 h70
  text "3" at 5724.84,8036.5 h70
  text "4" at 8231.51,8036.5 h70
  text "5" at 10730.5,8036.5 h70
  text "6" at 13235.5,8036.5 h70
  text "A" at -416.5,6893.5 h70
  text "A" at 14383.5,6893.5 h70
  text "B" at -416.5,4513.5 h70
  text "B" at 14383.5,4513.5 h70
  text "C" at -416.5,2138.5 h70
  text "C" at 14383.5,2138.5 h70
  text "PROJECT TITLE:" at 11343.5,277.5 h45
  text ".PRJ_Title" at 11393.5,144.17 h70
  text "DESIGNED FOR:" at 11343.5,-23.5 h45
  text ".PRJ_Customer" at 11393.5,-163.5 h70
  text "D" at -416.5,-231.5 h70
  text "D" at 14383.5,-231.5 h70
  text "FILE NAME:" at 11343.5,-323.5 h45
  text ".PCB_File_Name_No_Path" at 11393.5,-443.5 h70
  text "Texas Instruments (TI) and/or its licensors do not warrant the accuracy or completeness of this specification" at 6374,-605.34 h45
  text "ENGINEER:" at 11343.5,-613.5 h45
  text "LAYOUT BY:" at 12848.5,-613.5 h45
  text "or any information contained therein. TI and/or its licensors do not warrant that this design will meet" at 6329.01,-718 h45
  text ".PRJ_Engineer" at 11393.5,-768.49 h70
  text ".PCB_Layout" at 12899,-768.49 h70
  text "the specifications, will be suitable for your application or fit for any particular purpose, or will operate in" at 6329.01,-830.67 h45
  text ".Layer_Name" at 577,-858.49 h60
  text "ALTIUM DESIGNER VERSION:" at 12848.5,-923.5 h45
  text "an implementation. TI and/or its licensors do not warrant that the design is production worthy. You should" at 6329.01,-943.33 h45
  text "completely validate and test your design implementation to confirm the system functionality for your application." at 6374,-1056 h45
  text ".print_Scale" at 11393.5,-1056.83 h70
  text ".Application_BuildNumber" at 12899,-1056.83 h70
  text "1" at 739.84,-1263.5 h70
  text "2" at 3235.5,-1263.5 h70
  text "3" at 5724.84,-1263.5 h70
  text "4" at 8231.51,-1263.5 h70
  text "5" at 10730.5,-1263.5 h70
  text "6" at 13235.5,-1263.5 h70
M10 Fab Notes:
  drawing of 189 lines, arcs and shapes, not listed
  text "DESIGN INFORMATION" at 12382.02,6356.17 h60
  text "MIN. TRACK WIDTH:" at 11737.46,6224.05 h60
  text "8" at 12833.7,6224.05 h60
  text "MIL" at 12988.46,6224.05 h60
  text "MIN. CLEARANCE:" at 11737.46,6099.92 h60
  text "0.2" at 12773.7,6099.93 h60
  text "mm" at 12988.46,6099.92 h60
  text "MIN. VIA PAD SIZE:" at 11737.46,5975.8 h60
  text "24" at 12803.71,5975.8 h60
  text "MIL" at 12988.46,5975.8 h60
  text "0.05mm (2MIL)" at 12432.46,5845.9 h60
  text "MINIMUM ANNULAR RING" at 11408.23,5837.67 h60
  text "EXTERNAL" at 13140.46,5837.67 h60
  text "PER" at 11608.23,5727.55 h60
  text "IPC-D-275 CLASS 2 LEVEL C" at 11828.23,5727.54 h60
  text "MIL, HOLES" at 13316.46,5627.07 h60
  text "+/-" at 12924,5618.48 h60
  text "+/-" at 13778,5618.48 h60
  text "REGISTRATION TOLERANCES:" at 11408.23,5617.42 h60
  text "METAL" at 12608,5617.42 h60
  text "5" at 13184.2,5617.42 h60
  text "3" at 14017.2,5617.42 h60
  text "MIL" at 14133.46,5617.42 h60
  text "HOLE SIZE TOLERANCE (UNLESS OTHERWISE SPECIFIED):" at 11408.23,5519.1 h60
  text "+/-" at 13778,5516.23 h60
  text "3" at 14017.2,5515.17 h60
  text "MIL" at 14133.46,5515.17 h60
  text "MATERIAL:" at 11333.46,5377.52 h60
  text "FR-4 High Tg" at 12319.9,5249 h60
  text "X" at 12175.46,5241.01 h60
  text "FR-408" at 11754.46,5236.49 h60
  text "OTHER" at 13242.46,5236.49 h60
  text "40.4 MIL (1.0mm) +/-10%" at 12074.56,5093.46 h60
  text "X" at 11955,5090 h60
  text "40MIL" at 13725,5086 h72
  text "THICKNESS:" at 11408.23,5085.24 h60
  text "OTHER" at 13359.46,5085.24 h60
  text "TOLERANCE:" at 11408.23,4946.92 h60
  text "X" at 12256.46,4946.92 h60
  text "ANSI IPC-6012 TYPE 3 CLASS 2" at 12434.48,4946.92 h60
  text "OTHER +/-" at 12434.46,4802.73 h60
  text "BOW & TWIST:" at 11408.23,4657.54 h60
  text "X" at 12256.46,4657.54 h60
  text "ANSI IPC-6012 TYPE 3 CLASS 2" at 12434.48,4657.54 h60
  text "OTHER +/-" at 12434.46,4510.85 h60
  text "DRILLING:" at 11333.46,4380.23 h60
  text "NC_DRILL FILES" at 13094.46,4275.04 h60
  text "REFERENCE:" at 11408.23,4271.1 h60
  text "X" at 12065.46,4271.01 h60
  text "AS SHOWN" at 12243.46,4271.1 h60
  text "X" at 12966.46,4271.1 h60
  text "OTHER" at 13392.46,4128.85 h60
  text "PTH COPPER THICKNESS:" at 11407.91,4125.32 h60
  text "X" at 12547.14,4125.32 h60
  text "20-30 um" at 12675.14,4125.32 h60
  text "BOARD FINISH:" at 11333.46,3977.73 h60
  text "SILKSCREEN:" at 11488.68,3867.6 h60
  text "X" at 12446.46,3867.6 h60
  text "TOP" at 12563.46,3867.6 h60
  text "X" at 12956.46,3867.6 h60
  text "BOTTOM" at 13074.46,3867.6 h60
  text "SILKSCREEN COLOR:" at 11488.68,3712.41 h60
  text "X" at 12445.46,3712.41 h60
  text "WHITE" at 12563.46,3712.41 h60
  text "OTHER" at 13074.46,3712.41 h60
  text "X" at 12576.46,3568.96 h60
  text "GREEN" at 12694.46,3568.96 h60
  text "OTHER" at 13312.46,3568.96 h60
  text "SOLDER RESIST COLOR:" at 11488.68,3562.1 h60
  text "X" at 12576.46,3414.71 h60
  text "MATTE" at 12694.46,3414.71 h60
  text "SEMI-GLOSS" at 13312,3414.07 h60
  text "IMMERSION GOLD (ENIG)" at 12394.46,3241.94 h60
  text "ENEPIG" at 13732,3234.72 h60
  text "SURFACE FINISH:" at 11333.46,3233.72 h60
  text "X" at 12216.46,3233.72 h60
  text "IMM. TIN/SILVER OR EQUIV" at 11663,3096.4 h60
  text "OTHER" at 13094.46,3092.47 h60
  text "ARRAY/PANEL:" at 11333.46,2937.09 h60
  text "CUT AND TRIM PER M1 BOARD OUTLINE" at 12394.46,2928.87 h60
  text "N.C. ROUTE" at 12394.46,2792.9 h60
  text "X" at 13082.46,2792.9 h60
  text "V. SCORE" at 13260.46,2792.9 h60
  text "CERTIFICATION:" at 11333.46,2663.77 h60
  text "MATERIALS AND WORKMANSHIP FOR ALL PCBS" at 12058.46,2663.77 h60
  text "TO MEET OR EXCEED THE REQUIREMENTS OF:" at 12058.46,2569.71 h60
  text "X" at 11695.97,2441.08 h60
  text "ANSI IPC-A-600F CLASS ->" at 11823.96,2441.08 h60
  text "X" at 13471.97,2441.08 h60
  text "2" at 13581.96,2441.08 h60
  text "1" at 13266.96,2439.58 h60
  text "3" at 13935.96,2439.58 h60
  text "X" at 12507.97,2293.39 h60
  text "RoHS" at 12635.96,2293.39 h60
  text "OTHER" at 13280.36,2293.39 h60
  text "PER ORDER" at 13677.42,2293.39 h60
  text "ALL BOARDS MUST MEET OR EXCEED UL94-V0 REQUIREMENTS." at 11361,2139.57 h60
  text "PCB MUST BEAR THE UL94V-0 UL REGISTERED MATERIAL ID NUMBER" at 11361,2023.5 h60
  text "ADDITIONAL REQUIREMENTS:" at 11333.46,1854.08 h60
  text "MICROSECTION:" at 11408.23,1746.95 h60
  text "YES" at 12313.96,1746.95 h60
  text "REQUIRED" at 13175.46,1602.62 h60
  text "BARE BOARD ELEC. TEST:" at 11408.23,1599.76 h60
  text "NONE" at 12713.96,1599.76 h60
  text "X" at 13057.46,1599.76 h60
  text "PER ORDER" at 13767.46,1599.76 h60
  text "XX MIL VIAS REQUIRE NON-CONDUCTIVE FILL AND PLANARIZE" at 11576.38,1394.82 h59
  text "XX MIL VIAS REQUIRE CONDUCTIVE FILL AND PLANARIZE" at 11584.38,1290.84 h60
  text "OUTER XX MIL VIAS REQUIRE 50 OHM SINGLE-ENDED IMPEDANCE" at 11583.39,1127.46 h58
  text "LAYER 2 & 3 (INNER LAYERS) XX MIL WIDE, XX MIL SPACE / TRACES REQUIRE 100 OHM DIFFERENTIAL IMPEDANCE" at 11575.39,891.74 h60
  text ".Layer_Name" at 577,-858.49 h60
M11 Gerber Information:
  lines w10: -292,-930.17 6308,-930.17 ; -292,-726.83 6310,-726.83 ; -292,-523.5 -292,-1133.5 3713,-1133.5 6310,-1133.5 6310,-523.5 -291.5,-523.5 -291.5,-1133.5 1284,-1133.5 ; 2173,-1133.5 2173,-523.5 ; 3440,-726.83 3440,-523.5 ; 4280,-726.83 4280,-523.5 ; 4902,-1140 4902,-937.17
  text "ALL ARTWORK VIEWED FROM TOP SIDE" at -228.5,-655.67 h60
  text "BOARD #:" at 2248,-655.67 h60
  text ".PRJ_Number" at 2793.5,-655.67 h60
  text "REV:" at 3638,-655.67 h60
  text ".PCB_Rev" at 3929.5,-655.67 h60
  text "SVN REV:" at 4476,-655.67 h60
  text ".VersionControl_RevNumber" at 4982,-655.67 h60
  text "LAYER NAME =" at -228.5,-858.49 h60
  text "TID #:" at 2248,-859 h60
  text ".TID" at 2793.5,-859 h60
  text "PLOT NAME =" at -228.5,-1064.34 h60
  text ".plot_File_Name" at 577,-1064.34 h60
  text "GENERATED    :" at 2250,-1064.34 h60
  text ".Print_Date" at 3119.5,-1064.34 h60
  text ".Print_Time" at 3848.5,-1064.34 h60
  text "TEXAS INSTRUMENTS" at 5113,-1064.34 h60
M12 Stackup:
  drawing of 295 lines, arcs and shapes, not listed
  text "Layer" at 9791.2,7840 h60
  text "Name" at 10201.11,7840 h60
  text "Material" at 11140.85,7840 h60
  text "Thickness" at 12000.62,7840 h60
  text "Constant" at 12650.46,7840 h60
  text "Board Layer Stack" at 13220.32,7840 h60
  text "Top Overlay" at 10201.11,7720 h60
  text "Top Solder" at 10201.11,7600 h60
  text "Solder Resist" at 11140.85,7600 h60
  text "0.40mil" at 12000.62,7600 h60
  text "3.5" at 12650.46,7600 h60
  text "1" at 9791.2,7480 h60
  text "Top Layer" at 10201.11,7480 h60
  text "1.40mil" at 12000.62,7480 h60
  text "Dielectric 1" at 10201.11,7360 h60
  text "FR-4" at 11140.85,7360 h60
  text "8.00mil" at 12000.62,7360 h60
  text "4.2" at 12650.46,7360 h60
  text "2" at 9791.2,7240 h60
  text "Signal Layer 1" at 10201.11,7240 h60
  text "1.40mil" at 12000.62,7240 h60
  text "Dielectric 2" at 10201.11,7120 h60
  text "FR-4" at 11140.85,7120 h60
  text "18.00mil" at 12000.62,7120 h60
  text "4.2" at 12650.46,7120 h60
  text "3" at 9791.2,7000 h60
  text "Signal Layer 2" at 10201.11,7000 h60
  text "1.40mil" at 12000.62,7000 h60
  text "Dielectric 3" at 10201.11,6880 h60
  text "FR-4" at 11140.85,6880 h60
  text "8.00mil" at 12000.62,6880 h60
  text "4.2" at 12650.46,6880 h60
  text "4" at 9791.2,6760 h60
  text "Bottom Layer" at 10201.11,6760 h60
  text "1.40mil" at 12000.62,6760 h60
  text "Bottom Solder" at 10201.11,6640 h60
  text "Solder Resist" at 11140.85,6640 h60
  text "0.40mil" at 12000.62,6640 h60
  text "3.5" at 12650.46,6640 h60
  text "Bottom Overlay" at 10201.11,6520 h60
  text ".Layer_Name" at 577,-858.49 h60
M13 Component Bodies Top:
  text ".Layer_Name" at 577,-858.49 h60
M14 Component Bodies Bottom:
  text ".Layer_Name" at 577,-858.49 h60
M15 Courtyards Top:
  text ".Layer_Name" at 577,-858.49 h60
M16 Courtyards Bottom:
  text ".Layer_Name" at 577,-858.49 h60
Drill Drawing:
  circle w10: c5363.72,3691.43 r27.63
  circle w10: c5363.72,3194.15 r16.58
  circle w10: c5363.72,3194.15 r27.63
  lines w10: 5336.09,2434.42 5349.9,2434.42 5349.9,2420.6 5377.53,2420.6 5377.53,2434.42 5391.34,2434.42 5391.34,2462.04 5377.53,2462.04 5377.53,2475.86 5349.9,2475.86 5349.9,2462.04 5336.09,2462.04 5336.09,2434.42 ; 5336.09,2558.74 5349.9,2558.74 5363.72,2544.92 5377.53,2558.74 5391.34,2558.74 5377.53,2572.55 5391.34,2586.36 5377.53,2586.36 5363.72,2600.18 5349.9,2586.36 5336.09,2586.36 5349.9,2572.55 5336.09,2558.74 ; 5336.09,2669.24 5391.34,2669.24 5391.34,2724.5 5336.09,2724.5 5336.09,2669.24 ; 5336.09,2931.7 5349.9,2931.7 5349.9,2917.88 5377.53,2917.88 5377.53,2931.7 5391.34,2931.7 5391.34,2959.32 5377.53,2959.32 5377.53,2973.14 5349.9,2973.14 5349.9,2959.32 5336.09,2959.32 5336.09,2931.7 ; 5336.09,3042.2 5363.72,3056.02 5391.34,3042.2 5377.53,3069.83 5391.34,3097.46 5363.72,3083.64 5336.09,3097.46 5349.9,3069.83 5336.09,3042.2 ; 5336.09,3318.47 5363.72,3290.84 5391.34,3318.47 5363.72,3346.1 5336.09,3318.47 ; 5336.09,3539.48 5363.72,3553.3 5391.34,3539.48 5377.53,3567.11 5391.34,3594.74 5363.72,3580.92 5336.09,3594.74 5349.9,3567.11 5336.09,3539.48 ; 5347.14,2937.22 5355.43,2937.22 5355.43,2928.93 5372.01,2928.93 5372.01,2937.22 5380.29,2937.22 5380.29,2953.8 5372.01,2953.8 5372.01,2962.09 5355.43,2962.09 5355.43,2953.8 5347.14,2953.8 5347.14,2937.22 ; 5347.14,3550.53 5363.72,3558.82 5380.29,3550.53 5372.01,3567.11 5380.29,3583.69 5363.72,3575.4 5347.14,3583.69 5355.43,3567.11 5347.14,3550.53
  lines w12: 5286,2383.31 8517.49,2383.31 ; 5286,3875.15 8517.49,3875.15 ; 5623.86,2258.99 5623.86,3999.47 ; 5955.86,2258.99 5955.86,3999.47 ; 6592.43,2258.99 6592.43,3999.47 ; 6851.57,2258.99 6851.57,3999.47 ; 7226.72,2258.99 7226.72,3999.47 ; 7951.05,2258.99 7951.05,3999.47 ; 5286,2258.99 8517.49,2258.99 8517.49,3999.47 5286,3999.47 5286,2258.99
  text "Symbol" at 5360.59,3912.44 h72
  text "Quantity" at 5661.16,3912.44 h72
  text "Finished Hole Size" at 5993.16,3912.44 h72
  text "Plated" at 6629.72,3912.44 h72
  text "Hole Type" at 6888.86,3912.44 h72
  text "Drill Layer Pair" at 7264.02,3912.44 h72
  text "Hole Tolerance" at 7988.35,3912.44 h72
  text "5" at 5661.16,3788.12 h60
  text "7.87mil (0.200mm)" at 5993.16,3788.12 h60
  text "PTH" at 6629.72,3788.12 h60
  text "Round" at 6888.86,3788.12 h60
  text "Top Layer - Bottom Layer" at 7264.02,3788.12 h60
  text "D" at 5335.31,3778.13 h55.25
  text "8" at 5661.16,3663.8 h60
  text "8.00mil (0.203mm)" at 5993.16,3663.8 h60
  text "PTH" at 6629.72,3663.8 h60
  text "Round" at 6888.86,3663.8 h60
  text "Top Layer - Bottom Layer" at 7264.02,3663.8 h60
  text "54" at 5661.16,3539.48 h60
  text "11.81mil (0.300mm)" at 5993.16,3539.48 h60
  text "PTH" at 6629.72,3539.48 h60
  text "Round" at 6888.86,3539.48 h60
  text "Top Layer - Bottom Layer" at 7264.02,3539.48 h60
  text "2" at 5661.16,3415.16 h60
  text "25.59mil (0.650mm)" at 5993.16,3415.16 h60
  text "PTH" at 6629.72,3415.16 h60
  text "Round" at 6888.86,3415.16 h60
  text "Top Layer - Bottom Layer" at 7264.02,3415.16 h60
  text "C" at 5335.31,3405.17 h55.25
  text "6" at 5661.16,3290.84 h60
  text "33.47mil (0.850mm)" at 5993.16,3290.84 h60
  text "PTH" at 6629.72,3290.84 h60
  text "Round" at 6888.86,3290.84 h60
  text "Top Layer - Bottom Layer" at 7264.02,3290.84 h60
  text "2" at 5661.16,3166.52 h60
  text "35.43mil (0.900mm)" at 5993.16,3166.52 h60
  text "PTH" at 6629.72,3166.52 h60
  text "Round" at 6888.86,3166.52 h60
  text "Top Layer - Bottom Layer" at 7264.02,3166.52 h60
  text "2" at 5661.16,3042.2 h60
  text "37.40mil (0.950mm)" at 5993.16,3042.2 h60
  text "PTH" at 6629.72,3042.2 h60
  text "Round" at 6888.86,3042.2 h60
  text "Top Layer - Bottom Layer" at 7264.02,3042.2 h60
  text "9" at 5661.16,2917.88 h60
  text "39.37mil (1.000mm)" at 5993.16,2917.88 h60
  text "PTH" at 6629.72,2917.88 h60
  text "Round" at 6888.86,2917.88 h60
  text "Top Layer - Bottom Layer" at 7264.02,2917.88 h60
  text "2" at 5661.16,2793.56 h60
  text "41.34mil (1.050mm)" at 5993.16,2793.56 h60
  text "PTH" at 6629.72,2793.56 h60
  text "Round" at 6888.86,2793.56 h60
  text "Top Layer - Bottom Layer" at 7264.02,2793.56 h60
  text "A" at 5335.31,2783.57 h55.25
  text "6" at 5661.16,2669.24 h60
  text "49.21mil (1.250mm)" at 5993.16,2669.24 h60
  text "PTH" at 6629.72,2669.24 h60
  text "Round" at 6888.86,2669.24 h60
  text "Top Layer - Bottom Layer" at 7264.02,2669.24 h60
  text "4" at 5661.16,2544.92 h60
  text "53.15mil (1.350mm)" at 5993.16,2544.92 h60
  text "PTH" at 6629.72,2544.92 h60
  text "Round" at 6888.86,2544.92 h60
  text "Top Layer - Bottom Layer" at 7264.02,2544.92 h60
  text "3" at 5661.16,2420.6 h60
  text "63.00mil (1.600mm)" at 5993.16,2420.6 h60
  text "PTH" at 6629.72,2420.6 h60
  text "Round" at 6888.86,2420.6 h60
  text "Top Layer - Bottom Layer" at 7264.02,2420.6 h60
  text "103 Total" at 5661.16,2296.28 h60
  text ".Layer_Name" at 577,-858.49 h60
Mechanical 17:
  text ".Layer_Name" at 577,-858.49 h60
Mechanical 18:
  text ".Layer_Name" at 577,-858.49 h60
Mechanical 19:
  text ".Layer_Name" at 577,-858.49 h60

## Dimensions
0,-400 to 1000,-400 on M2 Board Dimensions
